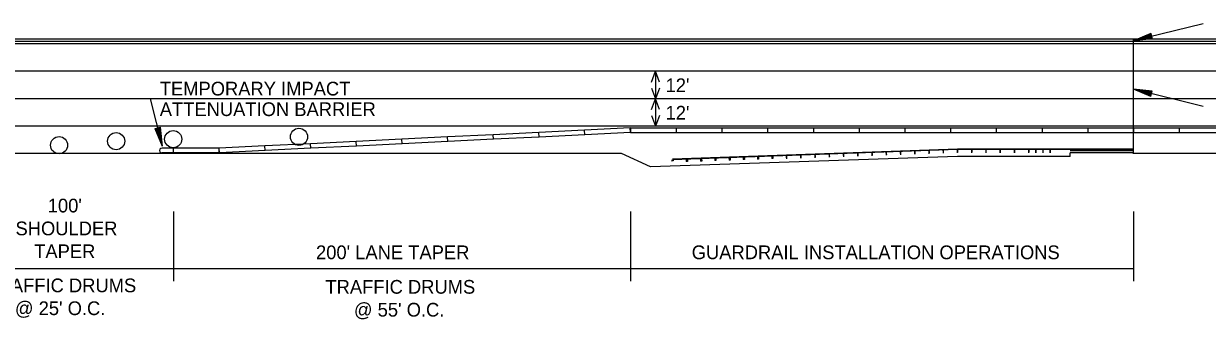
# Model space of a CAD drawing. Extents: x 1397271 to 1411271, y 376395 to 377888.
# Drawn here: x 1409762 to 1410415, y 376768 to 376931 of the extents above; entities that cross this region are included whole.
import ezdxf

# ---------------------------------------------------------------- set-up
doc = ezdxf.new("R2010")
doc.units = 0
for name, color, linetype in [('Default', 7, 'Continuous'), ('R_Border', 7, 'Continuous'), ('R_Dimension', 7, 'Continuous'), ('R_Draft', 7, 'Continuous'), ('R_Horz Alg', 7, 'Continuous'), ('R_MOT', 7, 'Continuous')]:
    doc.layers.add(name, color=color, linetype=linetype)

msp = doc.modelspace()

# ---------------------------------------------------------------- linework, layer by layer
at = {"layer": 'Default'}
for p, q in [((1410383.47, 376925.94), (1410373.79, 376921.98)), ((1410383.53, 376925.69), (1410375.47, 376922.39)), ((1410383.59, 376925.43), (1410377.2, 376922.81)), ((1410383.66, 376925.18), (1410378.87, 376923.22)), ((1410383.72, 376924.92), (1410380.57, 376923.63)), ((1410383.47, 376925.94), (1410384.2, 376922.92)), ((1410384.2, 376922.92), (1410373.79, 376921.98)), ((1410384.14, 376923.17), (1410375.47, 376922.39)), ((1410384.08, 376923.43), (1410377.2, 376922.81)), ((1410384.02, 376923.68), (1410378.87, 376923.22)), ((1410383.96, 376923.94), (1410380.57, 376923.63)), ((1410383.78, 376924.67), (1410382.25, 376924.04)), ((1410383.89, 376924.19), (1410382.25, 376924.04)), ((1410383.47, 376891.2), (1410373.79, 376895.16)), ((1410384.2, 376894.22), (1410373.79, 376895.16)), ((1410383.53, 376891.46), (1410375.47, 376894.75)), ((1410384.14, 376893.97), (1410375.47, 376894.75)), ((1410384.08, 376893.71), (1410377.2, 376894.33)), ((1410383.59, 376891.71), (1410377.2, 376894.33)), ((1410383.66, 376891.96), (1410378.87, 376893.92)), ((1410384.02, 376893.46), (1410378.87, 376893.92)), ((1410383.96, 376893.2), (1410380.57, 376893.51)), ((1410383.72, 376892.22), (1410380.57, 376893.51)), ((1410383.89, 376892.95), (1410382.25, 376893.1)), ((1410383.78, 376892.48), (1410382.25, 376893.1)), ((1410383.47, 376891.2), (1410384.2, 376894.22)), ((1409834.13, 376873.48), (1409837.15, 376874.23)), ((1409834.13, 376873.48), (1409838.13, 376863.82)), ((1409834.39, 376873.55), (1409837.71, 376865.49)), ((1409834.64, 376873.61), (1409837.28, 376867.22)), ((1409834.89, 376873.67), (1409836.87, 376868.89)), ((1409835.15, 376873.74), (1409836.45, 376870.59)), ((1409835.4, 376873.8), (1409836.03, 376872.27)), ((1409835.88, 376873.91), (1409836.03, 376872.27)), ((1409836.13, 376873.98), (1409836.45, 376870.59)), ((1409836.39, 376874.04), (1409836.87, 376868.89)), ((1409836.64, 376874.1), (1409837.28, 376867.22)), ((1409836.9, 376874.17), (1409837.71, 376865.49)), ((1409837.15, 376874.23), (1409838.13, 376863.82)), ((1410373.84, 376874.83), (1409924.14, 376874.83)), ((1409844.43, 376860.16), (1409838.12, 376860.16)), ((1409844.43, 376862.68), (1409838.13, 376862.68)), ((1410276.76, 376862.25), (1410119.63, 376856.6)), ((1410276.78, 376861.91), (1410119.64, 376856.25)), ((1410213.61, 376859.64), (1410213.93, 376859.65)), ((1410213.93, 376859.65), (1410214.24, 376859.67)), ((1410213.93, 376859.65), (1410213.95, 376859.02)), ((1410221.47, 376859.92), (1410221.79, 376859.94)), ((1410221.79, 376859.94), (1410222.1, 376859.95)), ((1410221.79, 376859.94), (1410221.81, 376859.31)), ((1410229.33, 376860.21), (1410229.64, 376860.21)), ((1410229.64, 376860.21), (1410229.96, 376860.23)), ((1410229.64, 376860.21), (1410229.67, 376859.59)), ((1410237.18, 376860.49), (1410237.5, 376860.5)), ((1410237.21, 376859.86), (1410237.51, 376859.87)), ((1410237.21, 376859.81), (1410237.53, 376859.82)), ((1410237.5, 376860.5), (1410237.8, 376860.51)), ((1410237.5, 376860.5), (1410237.51, 376859.87)), ((1410237.51, 376859.87), (1410237.84, 376859.88)), ((1410237.53, 376859.82), (1410237.84, 376859.83)), ((1410237.53, 376859.82), (1410237.55, 376859.2)), ((1410245.03, 376860.77), (1410245.35, 376860.78)), ((1410245.06, 376860.15), (1410245.37, 376860.15)), ((1410245.06, 376860.1), (1410245.38, 376860.1)), ((1410245.35, 376860.78), (1410245.66, 376860.8)), ((1410245.35, 376860.78), (1410245.37, 376860.15)), ((1410245.37, 376860.15), (1410245.69, 376860.17)), ((1410245.38, 376860.1), (1410245.69, 376860.12)), ((1410245.38, 376860.1), (1410245.39, 376859.47)), ((1410252.89, 376861.05), (1410253.21, 376861.07)), ((1410252.91, 376860.42), (1410253.23, 376860.44)), ((1410252.92, 376860.37), (1410253.23, 376860.39)), ((1410252.94, 376859.74), (1410253.25, 376859.76)), ((1410253.21, 376861.07), (1410253.52, 376861.07)), ((1410253.21, 376861.07), (1410253.23, 376860.44)), ((1410253.23, 376860.44), (1410253.54, 376860.45)), ((1410253.23, 376860.39), (1410253.54, 376860.39)), ((1410253.23, 376860.39), (1410253.25, 376859.76)), ((1410253.25, 376859.76), (1410253.57, 376859.77)), ((1410260.75, 376861.34), (1410261.06, 376861.34)), ((1410260.77, 376860.71), (1410261.09, 376860.72)), ((1410260.77, 376860.67), (1410261.09, 376860.67)), ((1410260.8, 376860.03), (1410261.11, 376860.04)), ((1410261.06, 376861.34), (1410261.38, 376861.36)), ((1410261.06, 376861.34), (1410261.09, 376860.72)), ((1410261.09, 376860.72), (1410261.4, 376860.73)), ((1410261.09, 376860.67), (1410261.4, 376860.68)), ((1410261.09, 376860.67), (1410261.11, 376860.04)), ((1410261.11, 376860.04), (1410261.42, 376860.05)), ((1410268.61, 376861.62), (1410268.92, 376861.63)), ((1410268.63, 376860.99), (1410268.95, 376861.01)), ((1410268.63, 376860.94), (1410268.95, 376860.96)), ((1410268.65, 376860.31), (1410268.97, 376860.33)), ((1410268.92, 376861.63), (1410269.24, 376861.64)), ((1410268.92, 376861.63), (1410268.95, 376861.01)), ((1410268.95, 376861.01), (1410269.26, 376861.01)), ((1410268.95, 376860.96), (1410269.26, 376860.96)), ((1410268.95, 376860.96), (1410268.97, 376860.33)), ((1410268.97, 376860.33), (1410269.28, 376860.33)), ((1410276.46, 376861.9), (1410276.78, 376861.91)), ((1410276.48, 376861.27), (1410276.8, 376861.28)), ((1410276.49, 376861.22), (1410276.8, 376861.23)), ((1410276.51, 376860.59), (1410276.82, 376860.6)), ((1410339.66, 376862.25), (1410276.76, 376862.25)), ((1410339.66, 376861.91), (1410276.76, 376861.91)), ((1410276.78, 376861.91), (1410277.09, 376861.92)), ((1410276.78, 376861.91), (1410276.8, 376861.28)), ((1410276.8, 376861.28), (1410277.11, 376861.29)), ((1410276.8, 376861.23), (1410277.11, 376861.24)), ((1410276.8, 376861.23), (1410276.82, 376860.6)), ((1410276.82, 376860.6), (1410277.14, 376860.61)), ((1410284.31, 376861.91), (1410284.62, 376861.91)), ((1410284.31, 376861.28), (1410284.62, 376861.28)), ((1410284.31, 376861.23), (1410284.62, 376861.23)), ((1410284.31, 376860.6), (1410284.62, 376860.6)), ((1410284.62, 376861.91), (1410284.94, 376861.91)), ((1410284.62, 376861.91), (1410284.62, 376861.28)), ((1410284.62, 376861.28), (1410284.94, 376861.28)), ((1410284.62, 376861.23), (1410284.94, 376861.23)), ((1410284.62, 376861.23), (1410284.62, 376860.6)), ((1410284.62, 376860.6), (1410284.94, 376860.6)), ((1410292.17, 376861.91), (1410292.49, 376861.91)), ((1410292.17, 376861.28), (1410292.49, 376861.28)), ((1410292.17, 376861.23), (1410292.49, 376861.23)), ((1410292.17, 376860.6), (1410292.49, 376860.6)), ((1410292.49, 376861.91), (1410292.8, 376861.91)), ((1410292.49, 376861.91), (1410292.49, 376861.28)), ((1410292.49, 376861.28), (1410292.8, 376861.28)), ((1410292.49, 376861.23), (1410292.8, 376861.23)), ((1410292.49, 376861.23), (1410292.49, 376860.6)), ((1410292.49, 376860.6), (1410292.8, 376860.6)), ((1410300.03, 376861.91), (1410300.35, 376861.91)), ((1410300.03, 376861.28), (1410300.35, 376861.28)), ((1410300.03, 376861.23), (1410300.35, 376861.23)), ((1410300.03, 376860.6), (1410300.35, 376860.6)), ((1410300.35, 376861.91), (1410300.66, 376861.91)), ((1410300.35, 376861.91), (1410300.35, 376861.28)), ((1410300.35, 376861.28), (1410300.66, 376861.28)), ((1410300.35, 376861.23), (1410300.66, 376861.23)), ((1410300.35, 376861.23), (1410300.35, 376860.6)), ((1410300.35, 376860.6), (1410300.66, 376860.6)), ((1410307.9, 376861.91), (1410308.21, 376861.91)), ((1410307.9, 376861.28), (1410308.21, 376861.28)), ((1410307.9, 376861.23), (1410308.21, 376861.23)), ((1410307.9, 376860.6), (1410308.21, 376860.6)), ((1410308.21, 376861.91), (1410308.52, 376861.91)), ((1410308.21, 376861.91), (1410308.21, 376861.28)), ((1410308.21, 376861.28), (1410308.52, 376861.28)), ((1410308.21, 376861.23), (1410308.52, 376861.23)), ((1410308.21, 376861.23), (1410308.21, 376860.6)), ((1410308.21, 376860.6), (1410308.52, 376860.6)), ((1410315.76, 376861.91), (1410316.07, 376861.91)), ((1410315.76, 376861.28), (1410316.07, 376861.28)), ((1410315.76, 376861.23), (1410316.07, 376861.23)), ((1410315.76, 376860.6), (1410316.07, 376860.6)), ((1410316.07, 376861.91), (1410316.39, 376861.91)), ((1410316.07, 376861.91), (1410316.07, 376861.28)), ((1410316.07, 376861.28), (1410316.39, 376861.28)), ((1410316.07, 376861.23), (1410316.39, 376861.23)), ((1410316.07, 376861.23), (1410316.07, 376860.6)), ((1410316.07, 376860.6), (1410316.39, 376860.6)), ((1410319.69, 376861.91), (1410320.01, 376861.91)), ((1410319.69, 376861.28), (1410320.01, 376861.28)), ((1410319.69, 376861.23), (1410320.01, 376861.23)), ((1410319.69, 376860.6), (1410320.01, 376860.6)), ((1410320.01, 376861.91), (1410320.32, 376861.91)), ((1410320.01, 376861.91), (1410320.01, 376861.28)), ((1410320.01, 376861.28), (1410320.32, 376861.28)), ((1410320.01, 376861.23), (1410320.32, 376861.23)), ((1410320.01, 376861.23), (1410320.01, 376860.6)), ((1410320.01, 376860.6), (1410320.32, 376860.6)), ((1410323.62, 376861.91), (1410323.93, 376861.91)), ((1410323.62, 376861.28), (1410323.93, 376861.28)), ((1410323.62, 376861.23), (1410323.93, 376861.23)), ((1410323.62, 376860.6), (1410323.93, 376860.6)), ((1410323.93, 376861.91), (1410324.25, 376861.91)), ((1410323.93, 376861.91), (1410323.93, 376861.28)), ((1410323.93, 376861.28), (1410324.25, 376861.28)), ((1410323.93, 376861.23), (1410324.25, 376861.23)), ((1410323.93, 376861.23), (1410323.93, 376860.6)), ((1410323.93, 376860.6), (1410324.25, 376860.6)), ((1410327.56, 376861.91), (1410327.87, 376861.91)), ((1410327.56, 376861.28), (1410327.87, 376861.28)), ((1410327.56, 376861.23), (1410327.87, 376861.23)), ((1410327.56, 376860.6), (1410327.87, 376860.6)), ((1410327.87, 376861.91), (1410328.18, 376861.91)), ((1410327.87, 376861.91), (1410327.87, 376861.28)), ((1410327.87, 376861.28), (1410328.18, 376861.28)), ((1410327.87, 376861.23), (1410328.18, 376861.23)), ((1410327.87, 376861.23), (1410327.87, 376860.6)), ((1410327.87, 376860.6), (1410328.18, 376860.6)), ((1410373.84, 376862.25), (1410338.9, 376862.25)), ((1410373.84, 376861.86), (1410338.9, 376861.86)), ((1410373.84, 376861.21), (1410338.9, 376861.21)), ((1410373.84, 376860.16), (1410338.9, 376860.16)), ((1410338.9, 376858.14), (1410338.9, 376860.16)), ((1410339.66, 376862.25), (1410339.66, 376861.91)), ((1410339.66, 376862.25), (1410342.05, 376862.25)), ((1410339.66, 376861.91), (1410342.05, 376861.91)), ((1410342.05, 376862.25), (1410342.05, 376861.91)), ((1410119.33, 376856.26), (1410119.35, 376855.63)), ((1410119.98, 376855.65), (1410119.35, 376855.63)), ((1410119.96, 376856.28), (1410119.98, 376855.65)), ((1410127.19, 376856.55), (1410127.23, 376855.29)), ((1410127.5, 376856.55), (1410127.19, 376856.55)), ((1410127.84, 376855.94), (1410127.21, 376855.92)), ((1410127.86, 376855.31), (1410127.23, 376855.29)), ((1410127.82, 376856.57), (1410127.5, 376856.55)), ((1410127.82, 376856.57), (1410127.86, 376855.31)), ((1410135.36, 376856.84), (1410135.04, 376856.82)), ((1410135.04, 376856.82), (1410135.09, 376855.57)), ((1410135.7, 376856.22), (1410135.07, 376856.2)), ((1410135.72, 376855.59), (1410135.09, 376855.57)), ((1410135.67, 376856.85), (1410135.36, 376856.84)), ((1410135.67, 376856.85), (1410135.72, 376855.59)), ((1410143.22, 376857.12), (1410142.89, 376857.11)), ((1410142.89, 376857.11), (1410142.94, 376855.86)), ((1410143.55, 376856.51), (1410142.93, 376856.48)), ((1410143.56, 376855.88), (1410142.94, 376855.86)), ((1410143.52, 376857.14), (1410143.22, 376857.12)), ((1410143.52, 376857.14), (1410143.56, 376855.88)), ((1410151.06, 376857.41), (1410150.75, 376857.39)), ((1410150.75, 376857.39), (1410150.79, 376856.13)), ((1410151.4, 376856.78), (1410150.77, 376856.76)), ((1410151.42, 376856.15), (1410150.79, 376856.13)), ((1410151.38, 376857.42), (1410151.06, 376857.41)), ((1410151.38, 376857.42), (1410151.42, 376856.15)), ((1410158.61, 376857.68), (1410158.65, 376856.43)), ((1410158.92, 376857.68), (1410158.61, 376857.68)), ((1410159.26, 376857.06), (1410158.63, 376857.05)), ((1410159.28, 376856.44), (1410158.65, 376856.43)), ((1410159.24, 376857.69), (1410158.92, 376857.68)), ((1410159.24, 376857.69), (1410159.28, 376856.44)), ((1410166.46, 376857.96), (1410166.51, 376856.7)), ((1410166.78, 376857.96), (1410166.46, 376857.96)), ((1410167.12, 376857.35), (1410166.49, 376857.33)), ((1410167.14, 376856.72), (1410166.51, 376856.7)), ((1410167.09, 376857.98), (1410166.78, 376857.96)), ((1410167.09, 376857.98), (1410167.14, 376856.72)), ((1410174.64, 376858.25), (1410174.32, 376858.23)), ((1410174.32, 376858.23), (1410174.37, 376856.98)), ((1410174.97, 376857.63), (1410174.35, 376857.6)), ((1410175, 376857), (1410174.37, 376856.98)), ((1410174.95, 376858.25), (1410174.64, 376858.25)), ((1410174.95, 376858.25), (1410175, 376857)), ((1410182.18, 376858.51), (1410182.5, 376858.52)), ((1410182.2, 376857.88), (1410182.52, 376857.89)), ((1410182.22, 376857.83), (1410182.52, 376857.84)), ((1410182.23, 376857.2), (1410182.55, 376857.21)), ((1410182.5, 376858.52), (1410182.81, 376858.53)), ((1410182.5, 376858.52), (1410182.52, 376857.89)), ((1410182.52, 376857.89), (1410182.83, 376857.91)), ((1410182.52, 376857.84), (1410182.85, 376857.86)), ((1410182.52, 376857.84), (1410182.55, 376857.21)), ((1410182.55, 376857.21), (1410182.86, 376857.23)), ((1410190.04, 376858.79), (1410190.35, 376858.81)), ((1410190.06, 376858.16), (1410190.38, 376858.18)), ((1410190.06, 376858.11), (1410190.38, 376858.13)), ((1410190.09, 376857.48), (1410190.4, 376857.5)), ((1410190.35, 376858.81), (1410190.67, 376858.81)), ((1410190.35, 376858.81), (1410190.38, 376858.18)), ((1410190.38, 376858.18), (1410190.69, 376858.18)), ((1410190.38, 376858.13), (1410190.69, 376858.14)), ((1410190.38, 376858.13), (1410190.4, 376857.5)), ((1410190.4, 376857.5), (1410190.71, 376857.5)), ((1410197.9, 376859.08), (1410198.21, 376859.08)), ((1410197.92, 376858.45), (1410198.23, 376858.46)), ((1410197.92, 376858.4), (1410198.24, 376858.4)), ((1410197.94, 376857.77), (1410198.26, 376857.78)), ((1410198.21, 376859.08), (1410198.53, 376859.1)), ((1410198.21, 376859.08), (1410198.23, 376858.46)), ((1410198.23, 376858.46), (1410198.55, 376858.47)), ((1410198.24, 376858.4), (1410198.55, 376858.42)), ((1410198.24, 376858.4), (1410198.26, 376857.78)), ((1410198.26, 376857.78), (1410198.57, 376857.79)), ((1410205.76, 376859.35), (1410206.07, 376859.37)), ((1410205.78, 376858.73), (1410206.09, 376858.74)), ((1410205.78, 376858.68), (1410206.09, 376858.69)), ((1410205.8, 376858.05), (1410206.12, 376858.06)), ((1410206.07, 376859.37), (1410206.38, 376859.38)), ((1410206.07, 376859.37), (1410206.09, 376858.74)), ((1410206.09, 376858.74), (1410206.41, 376858.75)), ((1410206.09, 376858.69), (1410206.41, 376858.7)), ((1410206.09, 376858.69), (1410206.12, 376858.06)), ((1410206.12, 376858.06), (1410206.43, 376858.07)), ((1410213.64, 376859.01), (1410213.95, 376859.02)), ((1410213.64, 376858.96), (1410213.95, 376858.97)), ((1410213.66, 376858.34), (1410213.97, 376858.34)), ((1410213.95, 376859.02), (1410214.27, 376859.04)), ((1410213.95, 376858.97), (1410214.27, 376858.99)), ((1410213.95, 376858.97), (1410213.97, 376858.34)), ((1410213.97, 376858.34), (1410214.29, 376858.36)), ((1410221.49, 376859.29), (1410221.81, 376859.31)), ((1410221.5, 376859.24), (1410221.81, 376859.26)), ((1410221.52, 376858.61), (1410221.83, 376858.63)), ((1410221.81, 376859.31), (1410222.12, 376859.31)), ((1410221.81, 376859.26), (1410222.12, 376859.26)), ((1410221.81, 376859.26), (1410221.83, 376858.63)), ((1410221.83, 376858.63), (1410222.15, 376858.64)), ((1410229.35, 376859.58), (1410229.67, 376859.59)), ((1410229.35, 376859.53), (1410229.67, 376859.53)), ((1410229.38, 376858.9), (1410229.69, 376858.91)), ((1410229.67, 376859.59), (1410229.98, 376859.6)), ((1410229.67, 376859.53), (1410229.98, 376859.55)), ((1410229.67, 376859.53), (1410229.69, 376858.91)), ((1410229.69, 376858.91), (1410230.01, 376858.92)), ((1410237.23, 376859.18), (1410237.55, 376859.2)), ((1410237.55, 376859.2), (1410237.86, 376859.2)), ((1410245.09, 376859.47), (1410245.39, 376859.47)), ((1410245.39, 376859.47), (1410245.72, 376859.49))]:
    msp.add_line(p, q, dxfattribs=at)
msp.add_arc((1409838.04, 376861.42), 1.26, 85.96283, 273.80647, dxfattribs=at)
at = {"layer": 'R_Dimension'}
for p, q in [((1410108.14, 376899.16), (1410110.29, 376905.09)), ((1410110.29, 376905.09), (1410110.29, 376874.83)), ((1410112.46, 376899.17), (1410110.29, 376905.09)), ((1410108.12, 376895.88), (1410110.29, 376889.96)), ((1410112.43, 376895.89), (1410110.29, 376889.96)), ((1410108.14, 376884.03), (1410110.29, 376889.96)), ((1410112.46, 376884.04), (1410110.29, 376889.96)), ((1410108.12, 376880.75), (1410110.29, 376874.83)), ((1410112.43, 376880.76), (1410110.29, 376874.83)), ((1409844.4, 376827.85), (1409844.4, 376789.32)), ((1410096.42, 376827.85), (1410096.42, 376789.32)), ((1410373.84, 376827.85), (1410373.84, 376789.32)), ((1410373.84, 376796.18), (1409718.31, 376796.18))]:
    msp.add_line(p, q, dxfattribs=at)
for points in [[(1410412.33, 376931.36), (1410373.79, 376921.98)], [(1410412.33, 376885.78), (1410373.79, 376895.16)], [(1409965.43, 376889.96), (1409831.51, 376889.96), (1409838.13, 376863.82)]]:
    msp.add_lwpolyline(points, dxfattribs=at)
at = {"layer": 'R_Draft'}
msp.add_line((1410373.84, 376860.16), (1410373.84, 376922.74), dxfattribs=at)
at = {"layer": 'R_Horz Alg'}
for p, q in [((1409970.37, 376922.74), (1409636.72, 376922.74)), ((1410658.78, 376921.48), (1409636.72, 376921.48)), ((1409970.37, 376920.22), (1409636.72, 376920.22)), ((1410245.24, 376922.74), (1409970.37, 376922.74)), ((1410245.24, 376920.22), (1409970.37, 376920.22)), ((1410658.78, 376922.74), (1410245.24, 376922.74)), ((1410658.78, 376920.22), (1410245.24, 376920.22)), ((1410658.78, 376905.09), (1409636.72, 376905.09)), ((1410658.78, 376889.96), (1409636.72, 376889.96)), ((1410658.78, 376874.83), (1409636.72, 376874.83)), ((1410091.54, 376859.7), (1409636.72, 376859.7)), ((1410658.78, 376859.7), (1410373.56, 376859.7)), ((1410338.9, 376858.14), (1410276.83, 376858.14))]:
    msp.add_line(p, q, dxfattribs=at)
for points in [[(1410107.42, 376852.38), (1410091.54, 376859.7)], [(1410276.83, 376858.14), (1410107.42, 376852.38)]]:
    msp.add_lwpolyline(points, dxfattribs=at)
at = {"layer": 'R_MOT'}
for p, q in [((1410096.33, 376873.87), (1410071.14, 376872.62)), ((1410096.45, 376871.35), (1410096.33, 376873.87)), ((1410096.45, 376873.87), (1410121.67, 376873.87)), ((1410096.45, 376873.87), (1410096.45, 376871.35)), ((1410121.67, 376873.87), (1410146.89, 376873.87)), ((1410121.67, 376873.87), (1410121.67, 376871.35)), ((1410121.67, 376873.87), (1410121.67, 376871.35)), ((1410146.89, 376873.87), (1410172.11, 376873.87)), ((1410146.89, 376873.87), (1410146.89, 376871.35)), ((1410146.89, 376873.87), (1410146.89, 376871.35)), ((1410172.11, 376873.87), (1410197.32, 376873.87)), ((1410172.11, 376873.87), (1410172.11, 376871.35)), ((1410172.11, 376873.87), (1410172.11, 376871.35)), ((1410197.32, 376873.87), (1410197.32, 376871.35)), ((1410197.32, 376873.87), (1410222.54, 376873.87)), ((1410197.32, 376873.87), (1410197.32, 376871.35)), ((1410222.54, 376873.87), (1410222.54, 376871.35)), ((1410222.54, 376873.87), (1410247.76, 376873.87)), ((1410222.54, 376873.87), (1410222.54, 376871.35)), ((1410247.76, 376873.87), (1410272.98, 376873.87)), ((1410247.76, 376873.87), (1410247.76, 376871.35)), ((1410247.76, 376873.87), (1410247.76, 376871.35)), ((1410272.98, 376873.87), (1410298.19, 376873.87)), ((1410272.98, 376873.87), (1410272.98, 376871.35)), ((1410272.98, 376873.87), (1410272.98, 376871.35)), ((1410298.19, 376873.87), (1410323.41, 376873.87)), ((1410298.19, 376873.87), (1410298.19, 376871.35)), ((1410298.19, 376873.87), (1410298.19, 376871.35)), ((1410323.41, 376873.87), (1410348.63, 376873.87)), ((1410323.41, 376873.87), (1410323.41, 376871.35)), ((1410323.41, 376873.87), (1410323.41, 376871.35)), ((1410348.63, 376873.87), (1410348.63, 376871.35)), ((1410348.63, 376873.87), (1410373.84, 376873.87)), ((1410348.63, 376873.87), (1410348.63, 376871.35)), ((1410373.84, 376873.87), (1410399.06, 376873.87)), ((1410373.84, 376873.87), (1410373.84, 376871.35)), ((1410373.84, 376873.87), (1410373.84, 376871.35)), ((1410399.06, 376873.87), (1410424.28, 376873.87)), ((1410399.06, 376873.87), (1410399.06, 376871.35)), ((1410399.06, 376873.87), (1410399.06, 376871.35)), ((1409945.21, 376866.41), (1409920.02, 376865.17)), ((1409970.4, 376867.65), (1409945.21, 376866.41)), ((1409945.33, 376863.89), (1409945.21, 376866.41)), ((1409945.33, 376863.89), (1409945.21, 376866.41)), ((1409995.58, 376868.9), (1409970.4, 376867.65)), ((1409970.52, 376865.13), (1409970.4, 376867.65)), ((1409970.52, 376865.13), (1409970.4, 376867.65)), ((1409995.71, 376866.38), (1409970.52, 376865.13)), ((1410020.77, 376870.14), (1409995.58, 376868.9)), ((1409995.71, 376866.38), (1409995.58, 376868.9)), ((1409995.71, 376866.38), (1409995.58, 376868.9)), ((1410020.89, 376867.62), (1409995.71, 376866.38)), ((1410045.96, 376871.38), (1410020.77, 376870.14)), ((1410020.89, 376867.62), (1410020.77, 376870.14)), ((1410020.89, 376867.62), (1410020.77, 376870.14)), ((1410046.08, 376868.86), (1410020.89, 376867.62)), ((1410071.14, 376872.62), (1410045.96, 376871.38)), ((1410046.08, 376868.86), (1410045.96, 376871.38)), ((1410046.08, 376868.86), (1410045.96, 376871.38)), ((1410071.27, 376870.1), (1410046.08, 376868.86)), ((1410071.27, 376870.1), (1410071.14, 376872.62)), ((1410071.27, 376870.1), (1410071.14, 376872.62)), ((1410096.45, 376871.35), (1410071.27, 376870.1)), ((1410096.45, 376871.35), (1410121.67, 376871.35)), ((1410121.67, 376871.35), (1410146.89, 376871.35)), ((1410146.89, 376871.35), (1410172.11, 376871.35)), ((1410172.11, 376871.35), (1410197.32, 376871.35)), ((1410197.32, 376871.35), (1410222.54, 376871.35)), ((1410222.54, 376871.35), (1410247.76, 376871.35)), ((1410247.76, 376871.35), (1410272.98, 376871.35)), ((1410272.98, 376871.35), (1410298.19, 376871.35)), ((1410298.19, 376871.35), (1410323.41, 376871.35)), ((1410323.41, 376871.35), (1410348.63, 376871.35)), ((1410348.63, 376871.35), (1410373.84, 376871.35)), ((1410373.84, 376871.35), (1410399.06, 376871.35)), ((1410399.06, 376871.35), (1410424.28, 376871.35)), ((1409869.65, 376862.68), (1409844.43, 376862.68)), ((1409844.43, 376860.16), (1409844.43, 376862.68)), ((1409869.65, 376860.16), (1409844.43, 376860.16)), ((1409894.84, 376863.92), (1409869.65, 376862.68)), ((1409869.65, 376860.16), (1409869.65, 376862.68)), ((1409869.77, 376860.16), (1409869.65, 376862.68)), ((1409894.96, 376861.41), (1409869.77, 376860.16)), ((1409920.02, 376865.17), (1409894.84, 376863.92)), ((1409894.96, 376861.41), (1409894.84, 376863.92)), ((1409894.96, 376861.41), (1409894.84, 376863.92)), ((1409920.15, 376862.65), (1409894.96, 376861.41)), ((1409920.15, 376862.65), (1409920.02, 376865.17)), ((1409920.15, 376862.65), (1409920.02, 376865.17)), ((1409945.33, 376863.89), (1409920.15, 376862.65)), ((1409970.52, 376865.13), (1409945.33, 376863.89))]:
    msp.add_line(p, q, dxfattribs=at)
for centre in [(1409913.64, 376868.96), (1409781.36, 376864.34), (1409812.81, 376866.59), (1409844.31, 376867.69)]:
    msp.add_circle(centre, 4.73, dxfattribs=at)

# ---------------------------------------------------------------- texts
at = {"layer": 'R_Border'}
for s, p in [('TEMPORARY IMPACT', (1409836.88, 376891.76)), ('ATTENUATION BARRIER', (1409836.88, 376880.42))]:
    msp.add_text(s, height=7.5652, dxfattribs=at).set_placement(p)
at = {"layer": 'R_Dimension'}
for s, height, p in [("12'", 7.565, (1410115.81, 376893.6)), ("12'", 7.565, (1410115.81, 376878.47)), ("100'", 7.565, (1409775.11, 376827.28)), ('SHOULDER', 7.565, (1409757.33, 376814.67)), ('TAPER', 7.565, (1409767.63, 376802.06)), ("200' LANE TAPER", 7.5652, (1409923.05, 376801.49)), ('GUARDRAIL INSTALLATION OPERATIONS', 7.5652, (1410130.23, 376801.49)), ('TRAFFIC DRUMS ', 7.5652, (1409741.28, 376783.26)), ('TRAFFIC DRUMS ', 7.5652, (1409928.23, 376782.46)), ("@ 25' O.C.", 7.565, (1409757.01, 376770.66)), ("@ 55' O.C.", 7.565, (1409943.96, 376769.85))]:
    msp.add_text(s, height=height, dxfattribs=at).set_placement(p)

doc.saveas('drawing.dxf')
